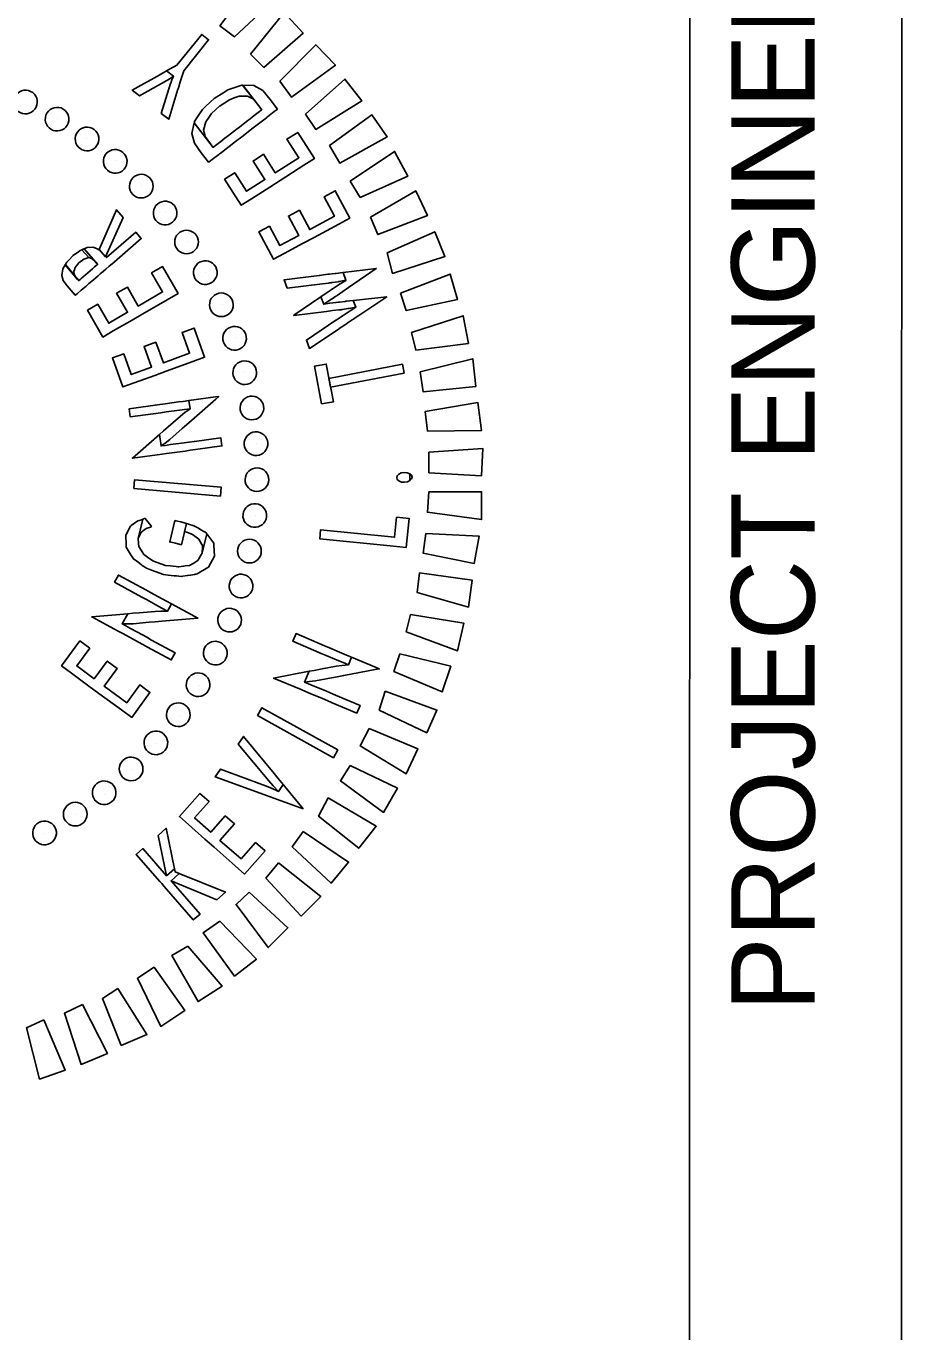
# Model space of a CAD drawing. Extents: x 264770 to 739672, y 157173 to 249791.
# Drawn here: x 733118 to 733478, y 170923 to 171459 of the extents above; entities that cross this region are included whole.
import ezdxf

# ---------------------------------------------------------------- set-up
doc = ezdxf.new("R2010")
doc.units = 0
for name, color, linetype in [('Old_Level_5', 7, 'Continuous'), ('Prop Conc Barrier Precast Reinforced Single Face', 7, 'Continuous'), ('Prop GRAU 350 Approach CELL', 7, 'Continuous')]:
    doc.layers.add(name, color=color, linetype=linetype)

msp = doc.modelspace()

# ---------------------------------------------------------------- linework, layer by layer
at = {"layer": 'Old_Level_5'}
msp.add_line((733390.87, 170751.16), (733390.99, 171812.95), dxfattribs=at)
at = {"layer": 'Prop Conc Barrier Precast Reinforced Single Face'}
for p, q in [((733131.44, 171421.44), (733131.44, 171421.44)), ((733143.44, 171413.04), (733143.44, 171413.04)), ((733155.44, 171404.04), (733155.44, 171404.04)), ((733165.94, 171393.84), (733165.94, 171393.84)), ((733175.84, 171382.74), (733175.84, 171382.74)), ((733184.54, 171370.74), (733184.54, 171370.74)), ((733192.04, 171358.14), (733192.04, 171358.14)), ((733198.94, 171344.94), (733198.94, 171344.94)), ((733204.34, 171331.44), (733204.34, 171331.44)), ((733208.24, 171317.34), (733208.24, 171317.34)), ((733211.24, 171302.34), (733211.24, 171302.34)), ((733213.04, 171287.94), (733213.04, 171287.94)), ((733213.64, 171272.94), (733213.64, 171272.94)), ((733212.44, 171258.24), (733212.44, 171258.24)), ((733210.04, 171243.54), (733210.04, 171243.54)), ((733207.04, 171229.44), (733207.04, 171229.44)), ((733202.24, 171215.34), (733202.24, 171215.34)), ((733196.24, 171201.84), (733196.24, 171201.84)), ((733189.64, 171188.64), (733189.64, 171188.64)), ((733181.24, 171176.34), (733181.24, 171176.34)), ((733171.94, 171164.64), (733171.94, 171164.64)), ((733161.74, 171154.14), (733161.74, 171154.14)), ((733150.64, 171143.94), (733150.64, 171143.94)), ((733138.94, 171135.54), (733138.94, 171135.54)), ((733126.04, 171127.74), (733126.04, 171127.74))]:
    msp.add_line(p, q, dxfattribs=at)
for points in [[(733198.04, 171459.54), (733211.24, 171477.24), (733219.94, 171469.74), (733204.04, 171455.04)], [(733210.64, 171447.84), (733224.44, 171464.94), (733232.24, 171456.54), (733216.04, 171442.44)], [(733183.19, 171441.01), (733193.39, 171453.76), (733190.54, 171456.01), (733180.34, 171443.34), (733176.14, 171441.01), (733178.91, 171438.84), (733178.31, 171437.34), (733178.31, 171437.26), (733177.86, 171435.99), (733177.79, 171435.84), (733173.96, 171423.54), (733177.04, 171421.14), (733180.79, 171433.44), (733180.86, 171433.59), (733181.31, 171434.86), (733181.31, 171434.94), (733181.76, 171436.51)], [(733222.64, 171436.74), (733237.34, 171451.74), (733245.44, 171443.34), (733227.44, 171430.14)], [(733177.64, 171437.94), (733178.91, 171438.84), (733176.14, 171441.01), (733174.71, 171440.19), (733174.71, 171440.19), (733174.71, 171440.19), (733173.51, 171439.51), (733173.36, 171439.44), (733162.04, 171433.14), (733164.96, 171430.81), (733176.29, 171437.11), (733176.44, 171437.19), (733177.56, 171437.86)], [(733221.51, 171425.19), (733221.66, 171425.34), (733218.59, 171429.24), (733215.59, 171432.91), (733211.99, 171435.01), (733207.41, 171435.16), (733215.21, 171425.04), (733215.14, 171424.96), (733214.99, 171424.81), (733214.31, 171424.29), (733212.14, 171422.64), (733210.49, 171421.36), (733208.91, 171420.16), (733205.31, 171417.31), (733205.24, 171417.31), (733201.56, 171414.46), (733200.06, 171413.34), (733198.41, 171411.99), (733196.24, 171410.34), (733195.56, 171409.81), (733195.41, 171409.66), (733195.26, 171409.59), (733187.46, 171419.64), (733186.49, 171415.29), (733187.61, 171411.31), (733190.39, 171407.41), (733193.39, 171403.51), (733193.54, 171403.59), (733194.81, 171404.56), (733197.51, 171406.66), (733197.66, 171406.74), (733197.81, 171406.89), (733198.49, 171407.41), (733200.66, 171409.06), (733202.31, 171410.41), (733203.81, 171411.54), (733207.56, 171414.39), (733207.56, 171414.39), (733211.16, 171417.24), (733212.74, 171418.44), (733214.39, 171419.71), (733216.56, 171421.36), (733217.24, 171421.89), (733217.39, 171422.04), (733217.54, 171422.11), (733220.31, 171424.29)], [(733211.31, 171429.61), (733211.76, 171429.39), (733207.26, 171435.16), (733206.96, 171435.16), (733206.14, 171434.86), (733203.36, 171433.96), (733201.26, 171433.21), (733199.61, 171432.16), (733199.69, 171432.16), (733195.71, 171429.69), (733195.71, 171429.69), (733192.26, 171426.46), (733190.91, 171425.19), (733189.64, 171423.31), (733188.06, 171420.91), (733187.61, 171420.16), (733187.54, 171419.86), (733187.46, 171419.64), (733194.44, 171410.64), (733191.96, 171414.09), (733191.81, 171414.76), (733191.29, 171416.71), (733192.19, 171420.01), (733193.46, 171421.89), (733194.59, 171423.46), (733198.04, 171426.61), (733198.11, 171426.61), (733201.94, 171429.16), (733203.89, 171429.91), (733205.91, 171430.66), (733209.36, 171430.66)], [(733211.76, 171429.39), (733214.39, 171426.09), (733207.41, 171435.16), (733207.26, 171435.16)], [(733233.14, 171423.24), (733249.34, 171437.64), (733256.24, 171428.64), (733237.34, 171416.94)], [(733243.04, 171410.34), (733260.44, 171422.94), (733266.74, 171413.94), (733247.24, 171403.14)], [(733232.46, 171402.24), (733236.81, 171405.01), (733229.99, 171415.74), (733225.56, 171412.96), (733230.44, 171405.31), (733220.76, 171399.09), (733215.89, 171406.74), (733211.61, 171403.96), (733216.49, 171396.39), (733208.99, 171391.59), (733204.11, 171399.16), (733199.91, 171396.46), (733206.81, 171385.81), (733211.01, 171388.44), (733218.51, 171393.24), (733222.79, 171396.01)], [(733251.44, 171395.64), (733269.74, 171407.94), (733275.14, 171397.74), (733255.64, 171389.04)], [(733246.79, 171378.09), (733251.36, 171380.56), (733245.36, 171391.74), (733240.79, 171389.26), (733245.06, 171381.31), (733234.94, 171375.84), (733230.66, 171383.79), (733226.16, 171381.39), (733230.44, 171373.44), (733222.64, 171369.24), (733218.36, 171377.19), (733213.94, 171374.86), (733220.01, 171363.61), (733224.36, 171366.01), (733232.24, 171370.21), (733236.66, 171372.61)], [(733259.84, 171380.94), (733278.44, 171391.74), (733283.24, 171381.54), (733262.84, 171373.74)], [(733151.09, 171364.59), (733158.29, 171380.79), (733155.51, 171383.94), (733148.46, 171367.66)], [(733153.64, 171361.66), (733165.71, 171372.09), (733163.46, 171374.71), (733151.39, 171364.29), (733148.46, 171367.66), (733148.31, 171367.44), (733147.64, 171367.89), (733145.91, 171368.56), (733143.51, 171368.49), (733142.31, 171367.96), (733147.86, 171361.51), (733147.79, 171361.51), (733147.71, 171361.44), (733147.11, 171360.91), (733146.51, 171360.46), (733145.69, 171359.71), (733143.74, 171357.99), (733143.74, 171357.99), (733141.86, 171356.41), (733140.96, 171355.59), (733140.59, 171355.36), (733140.14, 171354.91), (733140.06, 171354.84), (733134.51, 171361.36), (733133.54, 171359.71), (733133.09, 171357.01), (733133.69, 171354.91), (733135.34, 171352.74), (733138.64, 171348.84), (733138.86, 171348.99), (733139.54, 171349.51), (733141.11, 171350.94), (733142.46, 171352.06), (733142.54, 171352.14), (733142.99, 171352.51), (733143.36, 171352.81), (733144.26, 171353.64), (733146.14, 171355.21), (733146.14, 171355.21), (733148.09, 171356.86), (733148.91, 171357.69), (733149.51, 171358.14), (733150.11, 171358.66), (733150.19, 171358.74), (733150.19, 171358.74), (733151.16, 171359.56), (733152.59, 171360.84), (733153.26, 171361.36), (733153.41, 171361.51)], [(733266.74, 171366.24), (733286.24, 171374.94), (733290.44, 171364.74), (733268.84, 171357.84)], [(733143.44, 171364.06), (733144.19, 171364.29), (733141.34, 171367.51), (733140.66, 171367.21), (733139.76, 171366.54), (733137.66, 171365.11), (733137.66, 171365.04), (733136.01, 171363.31), (733135.11, 171362.41), (733134.89, 171361.96), (733134.59, 171361.44), (733138.49, 171356.86), (733137.96, 171358.44), (733138.11, 171358.89), (733138.56, 171360.31), (733140.14, 171362.19), (733140.14, 171362.19), (733142.16, 171363.69)], [(733146.66, 171362.86), (733147.41, 171362.04), (733142.31, 171367.96), (733142.31, 171367.96), (733142.16, 171367.89), (733141.34, 171367.51), (733144.19, 171364.29), (733145.61, 171363.84)], [(733139.61, 171355.36), (733138.49, 171356.86), (733134.59, 171361.44), (733134.51, 171361.36)], [(733176.36, 171346.96), (733180.86, 171349.59), (733174.49, 171360.61), (733169.99, 171357.99), (733174.49, 171350.19), (733164.51, 171344.41), (733160.01, 171352.21), (733155.59, 171349.66), (733160.09, 171341.86), (733152.36, 171337.36), (733147.86, 171345.16), (733143.59, 171342.69), (733149.96, 171331.66), (733154.24, 171334.21), (733161.96, 171338.64), (733166.39, 171341.19)], [(733249.71, 171354.99), (733249.79, 171354.99), (733248.59, 171358.21), (733248.51, 171358.21), (733245.81, 171357.84), (733245.44, 171357.84), (733245.29, 171357.76), (733242.89, 171357.54), (733242.89, 171357.46), (733242.81, 171357.46), (733242.36, 171357.46), (733241.54, 171357.31), (733241.39, 171357.31), (733238.91, 171357.01), (733238.84, 171357.01), (733224.36, 171355.21), (733225.64, 171351.76), (733240.11, 171353.56), (733240.19, 171353.56), (733242.66, 171353.86), (733242.81, 171353.94), (733243.64, 171354.01), (733244.01, 171354.09), (733244.16, 171354.09), (733246.56, 171354.39), (733246.71, 171354.46), (733247.01, 171354.46)], [(733250.84, 171352.06), (733262.24, 171359.86), (733248.59, 171358.21), (733249.79, 171354.99), (733249.71, 171354.91), (733249.71, 171354.91), (733247.39, 171353.56), (733247.09, 171353.34), (733246.94, 171353.26), (733244.99, 171351.91), (733244.84, 171351.91), (733244.54, 171351.69), (733243.79, 171351.16), (733243.71, 171351.09), (733241.61, 171349.66), (733241.61, 171349.66), (733239.51, 171348.24), (733240.64, 171345.16), (733242.74, 171346.51), (733242.81, 171346.51), (733244.91, 171347.94), (733244.99, 171348.01), (733245.74, 171348.46), (733246.04, 171348.69), (733246.11, 171348.76), (733248.14, 171350.11), (733248.29, 171350.26), (733248.51, 171350.41), (733250.84, 171351.99)], [(733272.14, 171349.74), (733292.54, 171357.54), (733295.54, 171347.04), (733274.54, 171342.54)], [(733251.14, 171343.44), (733253.84, 171343.89), (733252.79, 171346.66), (733250.01, 171346.36), (733249.71, 171346.36), (733249.49, 171346.29), (733247.16, 171346.06), (733247.01, 171346.06), (733246.64, 171345.99), (733245.74, 171345.91), (733245.66, 171345.91), (733243.11, 171345.61), (733243.11, 171345.54), (733240.64, 171345.16), (733239.51, 171348.24), (733228.34, 171340.66), (733228.34, 171340.59), (733241.76, 171342.24), (733244.24, 171342.54), (733244.24, 171342.54), (733246.79, 171342.84), (733246.94, 171342.84), (733247.76, 171342.91), (733248.14, 171342.99), (733248.29, 171342.99), (733250.61, 171343.36), (733250.84, 171343.36)], [(733255.11, 171340.59), (733266.51, 171348.16), (733252.86, 171346.66), (733252.79, 171346.66), (733253.84, 171343.89), (733251.51, 171342.46), (733251.21, 171342.24), (733251.06, 171342.16), (733249.04, 171340.81), (733248.96, 171340.81), (733248.66, 171340.59), (733247.91, 171340.06), (733247.84, 171339.99), (733245.74, 171338.64), (733245.74, 171338.64), (733245.66, 171338.56), (733245.66, 171338.56), (733233.51, 171330.46), (733234.79, 171327.01), (733246.94, 171335.11), (733247.01, 171335.19), (733249.11, 171336.54), (733249.19, 171336.61), (733249.94, 171337.14), (733250.24, 171337.29), (733250.31, 171337.36), (733252.34, 171338.71), (733252.49, 171338.79), (733252.79, 171339.01), (733255.04, 171340.51)], [(733276.64, 171333.54), (733297.94, 171340.44), (733300.04, 171329.04), (733278.44, 171326.34)], [(733186.86, 171321.61), (733191.74, 171323.41), (733187.39, 171335.34), (733182.51, 171333.54), (733185.59, 171325.06), (733174.79, 171321.09), (733171.64, 171329.56), (733166.91, 171327.84), (733169.99, 171319.36), (733161.59, 171316.29), (733158.51, 171324.76), (733153.86, 171323.11), (733158.21, 171311.19), (733162.86, 171312.84), (733171.26, 171315.91), (733175.99, 171317.64)], [(733239.74, 171304.21), (733244.69, 171305.11), (733241.69, 171320.56), (733236.81, 171319.66)], [(733243.49, 171311.04), (733273.64, 171316.89), (733272.96, 171320.49), (733242.81, 171314.71)], [(733280.24, 171317.34), (733301.84, 171322.74), (733303.04, 171311.34), (733281.44, 171309.24)], [(733183.49, 171301.89), (733185.74, 171302.19), (733185.29, 171305.56), (733182.96, 171305.26), (733181.01, 171305.04), (733175.54, 171304.29), (733173.36, 171303.99), (733160.76, 171302.26), (733161.21, 171298.89), (733173.81, 171300.61), (733175.99, 171300.91), (733181.46, 171301.66)], [(733196.31, 171306.16), (733197.51, 171307.21), (733196.16, 171307.06), (733185.29, 171305.56), (733185.74, 171302.19), (733183.64, 171300.69), (733181.84, 171299.19), (733176.81, 171294.76), (733174.86, 171293.11), (733173.21, 171291.69), (733173.89, 171286.96), (733175.54, 171288.09), (733177.49, 171289.66), (733182.51, 171294.09), (733184.31, 171295.66), (733186.41, 171297.46)], [(733282.34, 171301.14), (733303.94, 171304.74), (733305.44, 171293.34), (733283.24, 171293.04)], [(733188.06, 171285.46), (733198.86, 171286.96), (733198.41, 171290.26), (733187.54, 171288.84), (733185.29, 171288.46), (733183.34, 171288.24), (733177.79, 171287.49), (733175.69, 171287.19), (733173.89, 171286.96), (733173.21, 171291.69), (733162.11, 171281.94), (733174.34, 171283.59), (733176.14, 171283.81), (733178.24, 171284.11), (733183.79, 171284.86), (733185.74, 171285.16)], [(733283.84, 171284.34), (733306.04, 171285.84), (733305.44, 171274.74), (733283.84, 171275.94)], [(733162.71, 171269.41), (733198.26, 171266.34), (733198.56, 171270.01), (733163.01, 171273.09)], [(733275.06, 171272.19), (733276.04, 171272.71), (733275.96, 171275.56), (733274.91, 171275.94), (733273.71, 171276.09), (733272.51, 171275.86), (733271.46, 171275.41), (733270.79, 171274.74), (733270.64, 171273.99), (733270.86, 171273.16), (733271.54, 171272.56), (733272.59, 171272.11), (733273.86, 171272.04)], [(733276.71, 171273.39), (733276.94, 171274.14), (733276.71, 171274.89), (733275.96, 171275.56), (733276.04, 171272.71)], [(733283.84, 171268.14), (733305.44, 171268.14), (733305.44, 171256.74), (733283.24, 171259.74)], [(733193.39, 171237.16), (733195.79, 171241.74), (733195.49, 171246.16), (733195.49, 171247.06), (733192.64, 171250.89), (733190.76, 171243.01), (733190.76, 171242.94), (733189.79, 171241.36), (733189.64, 171240.99), (733188.96, 171239.94), (733187.01, 171238.74), (733185.59, 171237.91), (733183.79, 171237.69), (733183.19, 171237.61), (733183.04, 171237.54), (733181.09, 171237.31), (733180.79, 171237.24), (733180.11, 171237.39), (733177.64, 171237.69), (733175.69, 171237.91), (733175.61, 171237.91), (733170.74, 171239.64), (733168.86, 171240.91), (733167.14, 171242.11), (733167.14, 171242.11), (733166.84, 171242.34), (733165.64, 171244.21), (733164.66, 171245.71), (733164.66, 171245.71), (733164.66, 171245.71), (733164.59, 171246.84), (733164.44, 171248.94), (733166.31, 171256.89), (733166.31, 171256.81), (733164.36, 171256.21), (733161.59, 171254.26), (733161.59, 171254.26), (733161.36, 171254.04), (733159.34, 171250.29), (733159.34, 171250.29), (733159.49, 171246.24), (733159.56, 171245.41), (733161.21, 171242.71), (733162.49, 171240.61), (733162.49, 171240.61), (733163.09, 171240.24), (733163.31, 171240.01), (733163.31, 171240.01), (733164.51, 171239.19), (733165.86, 171238.14), (733166.16, 171237.91), (733167.89, 171236.71), (733169.91, 171235.96), (733174.79, 171234.16), (733174.79, 171234.16), (733176.74, 171233.94), (733179.21, 171233.64), (733179.89, 171233.56), (733180.19, 171233.56), (733182.06, 171233.34), (733182.21, 171233.34), (733182.81, 171233.41), (733184.61, 171233.71), (733185.89, 171233.94), (733187.61, 171234.16), (733188.06, 171234.24), (733188.14, 171234.24), (733188.74, 171234.39), (733188.74, 171234.39), (733193.09, 171237.01)], [(733169.46, 171253.66), (733169.91, 171253.89), (733169.61, 171254.26), (733168.41, 171255.84), (733167.36, 171257.19), (733167.36, 171257.19), (733166.99, 171257.11), (733166.31, 171256.89), (733164.44, 171248.94), (733165.71, 171251.49), (733166.09, 171251.79), (733166.09, 171251.79), (733167.74, 171253.06)], [(733179.81, 171246.99), (733182.21, 171246.39), (733184.24, 171255.09), (733181.91, 171255.76), (733179.96, 171256.21), (733179.96, 171256.21), (733179.51, 171256.29), (733177.41, 171247.51), (733177.86, 171247.44), (733177.94, 171247.44)], [(733269.36, 171245.79), (733274.54, 171245.26), (733275.74, 171257.11), (733270.56, 171257.64), (733269.74, 171249.46), (733239.36, 171252.54), (733238.99, 171248.86)], [(733190.76, 171243.09), (733190.76, 171243.01), (733192.64, 171250.89), (733192.64, 171250.89), (733192.19, 171251.41), (733192.11, 171251.49), (733191.74, 171251.71), (733190.24, 171252.54), (733189.19, 171253.14), (733187.61, 171254.04), (733187.09, 171254.34), (733186.94, 171254.34), (733185.14, 171254.86), (733184.91, 171254.94), (733184.24, 171255.09), (733183.49, 171251.71), (733184.16, 171251.56), (733184.39, 171251.49), (733186.11, 171250.89), (733186.26, 171250.81), (733186.79, 171250.59), (733188.29, 171249.54), (733189.34, 171248.71), (733190.54, 171246.54), (733190.84, 171246.09), (733190.84, 171245.56)], [(733282.64, 171251.04), (733304.54, 171249.84), (733302.44, 171238.74), (733281.44, 171242.94)], [(733279.94, 171234.84), (733301.54, 171231.84), (733300.04, 171220.74), (733279.04, 171226.74)], [(733174.41, 171220.21), (733176.51, 171219.16), (733178.09, 171222.09), (733176.06, 171223.21), (733174.34, 171224.19), (733169.46, 171226.81), (733167.59, 171227.86), (733156.34, 171233.94), (733154.76, 171231.01), (733165.94, 171224.86), (733167.81, 171223.89), (733172.69, 171221.19)], [(733168.34, 171204.31), (733178.01, 171199.06), (733179.59, 171201.99), (733169.99, 171207.24), (733167.96, 171208.36), (733166.24, 171209.34), (733161.29, 171211.96), (733159.41, 171213.01), (733157.84, 171213.91), (733160.16, 171218.04), (733145.39, 171216.76), (733156.26, 171210.91), (733157.84, 171210.01), (733159.71, 171209.04), (733164.59, 171206.34), (733166.31, 171205.36)], [(733187.31, 171216.09), (733188.96, 171216.24), (733187.76, 171216.84), (733178.09, 171222.09), (733176.51, 171219.16), (733173.81, 171219.16), (733171.49, 171219.01), (733164.81, 171218.41), (733162.26, 171218.26), (733160.16, 171218.04), (733157.84, 171213.91), (733159.86, 171213.84), (733162.34, 171213.91), (733169.01, 171214.51), (733171.41, 171214.66), (733174.19, 171214.96)], [(733276.34, 171217.74), (733298.24, 171214.14), (733295.54, 171202.74), (733274.54, 171210.54)], [(733248.59, 171198.01), (733250.76, 171197.11), (733252.11, 171200.19), (733249.94, 171201.09), (733248.14, 171201.91), (733242.96, 171204.09), (733241.01, 171204.91), (733229.31, 171209.86), (733227.96, 171206.71), (733239.66, 171201.76), (733241.69, 171200.94), (733246.79, 171198.76)], [(733157.61, 171178.51), (733161.81, 171175.44), (733169.31, 171185.71), (733165.11, 171188.79), (733159.79, 171181.51), (733150.49, 171188.34), (733155.81, 171195.61), (733151.76, 171198.61), (733146.36, 171191.34), (733139.24, 171196.59), (733144.56, 171203.86), (733140.51, 171206.86), (733133.01, 171196.59), (733137.06, 171193.66), (733144.19, 171188.34), (733148.31, 171185.34)], [(733261.79, 171195.09), (733263.44, 171195.39), (733262.16, 171195.99), (733252.11, 171200.19), (733250.76, 171197.11), (733248.14, 171196.81), (733245.81, 171196.51), (733239.29, 171195.24), (733236.74, 171194.79), (733234.64, 171194.41), (733232.76, 171189.99), (733234.79, 171190.14), (733237.26, 171190.51), (733243.79, 171191.71), (733246.19, 171192.16), (733248.89, 171192.69)], [(733271.84, 171201.54), (733292.84, 171196.44), (733289.24, 171185.94), (733269.44, 171194.34)], [(733244.16, 171181.51), (733254.29, 171177.24), (733255.56, 171180.39), (733245.51, 171184.59), (733243.34, 171185.56), (733241.54, 171186.31), (733236.36, 171188.49), (733234.41, 171189.31), (733232.76, 171189.99), (733234.64, 171194.41), (733220.09, 171191.64), (733231.41, 171186.91), (733233.14, 171186.16), (733235.09, 171185.34), (733240.19, 171183.16), (733242.06, 171182.41)], [(733265.84, 171186.24), (733287.14, 171178.44), (733282.94, 171169.14), (733263.44, 171178.44)], [(733213.49, 171176.19), (733244.61, 171158.86), (733246.41, 171162.09), (733215.29, 171179.41)], [(733259.24, 171170.94), (733279.34, 171162.54), (733274.54, 171152.34), (733255.64, 171163.74)], [(733219.86, 171147.31), (733222.11, 171145.06), (733224.06, 171147.84), (733221.96, 171150.31), (733220.24, 171152.41), (733220.24, 171152.41), (733207.71, 171167.64), (733205.54, 171164.49), (733218.14, 171149.41)], [(733220.16, 171142.29), (733232.16, 171137.94), (733224.06, 171147.84), (733222.11, 171145.06), (733219.26, 171146.41), (733216.71, 171147.39), (733198.26, 171154.21), (733196.01, 171151.06), (733214.54, 171144.31), (733217.09, 171143.41)], [(733251.44, 171155.64), (733270.94, 171146.34), (733265.24, 171136.44), (733247.54, 171149.34)], [(733204.26, 171114.54), (733208.16, 171111.09), (733216.56, 171120.61), (733212.66, 171124.06), (733206.74, 171117.31), (733198.04, 171124.89), (733204.04, 171131.71), (733200.21, 171135.01), (733194.29, 171128.26), (733187.61, 171134.19), (733193.54, 171140.94), (733189.79, 171144.24), (733181.39, 171134.71), (733185.14, 171131.41), (733191.81, 171125.49), (733195.64, 171122.19)], [(733242.44, 171142.44), (733262.24, 171130.74), (733255.04, 171121.74), (733238.54, 171134.94)], [(733172.61, 171126.91), (733176.14, 171110.41), (733179.44, 171113.26), (733175.99, 171129.91)], [(733232.24, 171128.64), (733250.84, 171116.04), (733243.64, 171107.34), (733227.74, 171122.34)], [(733175.16, 171105.99), (733187.09, 171092.26), (733189.86, 171094.66), (733177.94, 171108.39), (733181.31, 171111.31), (733179.66, 171111.99), (733179.44, 171113.26), (733176.14, 171110.41), (733166.39, 171121.59), (733163.61, 171119.11), (733173.36, 171108.01), (733174.11, 171107.19)], [(733177.94, 171108.39), (733196.69, 171100.59), (733200.29, 171103.74), (733181.31, 171111.31)], [(733222.04, 171115.74), (733239.44, 171101.94), (733231.34, 171093.84), (733216.94, 171109.44)], [(733210.04, 171103.74), (733225.94, 171089.04), (733217.84, 171080.94), (733204.64, 171098.64)], [(733198.04, 171091.74), (733213.04, 171076.14), (733204.04, 171069.24), (733191.14, 171086.94)], [(733184.84, 171081.54), (733198.94, 171065.04), (733189.04, 171058.74), (733178.24, 171077.64)], [(733171.04, 171072.84), (733183.64, 171055.14), (733173.74, 171048.54), (733164.14, 171068.34)], [(733156.04, 171064.14), (733168.04, 171045.24), (733157.54, 171040.74), (733149.74, 171059.94)], [(733141.64, 171057.54), (733151.84, 171037.44), (733141.04, 171032.94), (733134.14, 171053.94)], [(733125.74, 171051.24), (733134.44, 171030.54), (733123.94, 171026.94), (733118.54, 171047.94)]]:
    msp.add_lwpolyline(points, close=True, dxfattribs=at)
for centre, major_axis in [((733118.18, 171428.22), (2.13, 4.37)), ((733131.16, 171421.17), (2.5, 4.17)), ((733143.47, 171413.02), (2.86, 3.93)), ((733155.03, 171403.83), (3.19, 3.67)), ((733165.74, 171393.66), (3.5, 3.38)), ((733175.53, 171382.6), (3.78, 3.06)), ((733184.31, 171370.73), (4.03, 2.72)), ((733192.03, 171358.14), (4.25, 2.36)), ((733198.62, 171344.92), (4.44, 1.98)), ((733204.03, 171331.18), (4.6, 1.58)), ((733208.23, 171317.02), (4.72, 1.18)), ((733211.17, 171302.55), (4.8, 0.76)), ((733212.84, 171287.87), (4.85, 0.34)), ((733213.23, 171273.11), (4.86, -0.08)), ((733212.33, 171258.37), (4.83, -0.51)), ((733210.15, 171243.76), (4.77, -0.93)), ((733206.7, 171229.4), (4.67, -1.34)), ((733202.01, 171215.4), (4.54, -1.74)), ((733196.12, 171201.85), (4.37, -2.13)), ((733189.08, 171188.87), (4.17, -2.5)), ((733180.93, 171176.56), (3.93, -2.86)), ((733171.73, 171165), (3.67, -3.19)), ((733161.57, 171154.29), (3.38, -3.5)), ((733150.5, 171144.5), (3.06, -3.78)), ((733138.63, 171135.72), (2.72, -4.03)), ((733126.04, 171128), (2.36, -4.25))]:
    msp.add_ellipse(centre, major_axis=major_axis, ratio=0.999708, dxfattribs=at)
at = {"layer": 'Prop GRAU 350 Approach CELL'}
msp.add_lwpolyline([(733477.8, 169871.02), (733478.05, 171822.91)], dxfattribs=at)

# ---------------------------------------------------------------- texts
at = {"layer": 'Old_Level_5'}
msp.add_text('PROJECT ENGINEER', height=34.1905, rotation=89.994, dxfattribs=at).set_placement((733442.2, 171054.67))

doc.saveas('drawing.dxf')
